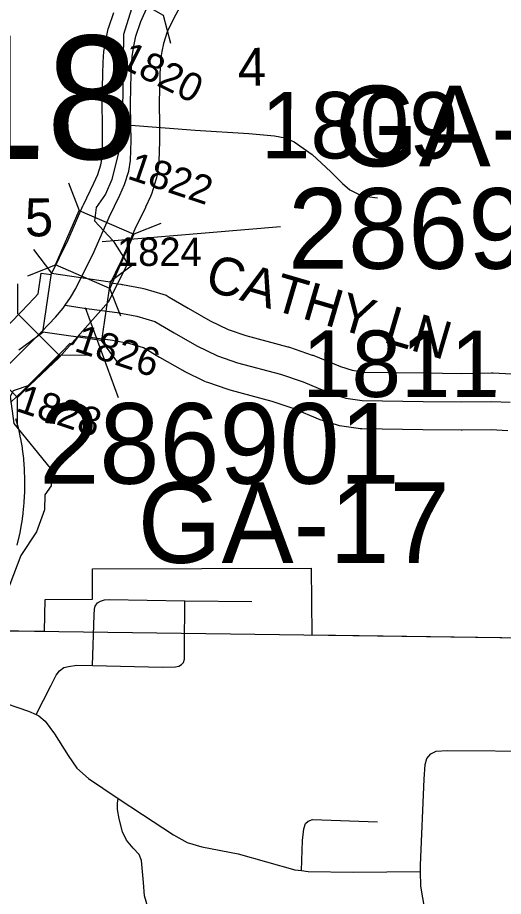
# Model space of a CAD drawing. Extents: x -132.8 to -73.3, y -60 to -26.
# Drawn here: x -121.403 to -120.892, y -47.631 to -46.704 of the extents above; entities that cross this region are included whole.
import ezdxf

# ---------------------------------------------------------------- set-up
doc = ezdxf.new("R2010")
doc.units = 0
for name, color, linetype in [('tdCoCityStreetMinor', 7, 'Continuous'), ('tdCoCorpBndry', 7, 'Continuous'), ('tdCoHydroRiver', 7, 'Continuous'), ('tdCoSecRdNmbr', 7, 'Continuous'), ('tdCoSecRdTxt', 7, 'Continuous'), ('tdCoSecRteBand', 7, 'Continuous'), ('tdCoSecRteCL', 7, 'Continuous'), ('tdCoSectLine', 7, 'Continuous'), ('tdCoSectLinePart', 7, 'Continuous'), ('tdCoSectNmbr', 7, 'Continuous'), ('tdCoStrucSec', 7, 'Continuous'), ('tdCoStrucSecCoName', 7, 'Continuous'), ('tdCoStrucSecFHWANum', 7, 'Continuous'), ('tdCoSurfBitum', 7, 'Continuous'), ('tdCoSurfGravelUnbanded', 7, 'Continuous')]:
    doc.layers.add(name, color=color, linetype=linetype)

msp = doc.modelspace()

# ---------------------------------------------------------------- linework, layer by layer
at = {"layer": 'tdCoCityStreetMinor'}
msp.add_line((-121.22694, -47.31903), (-121.15653, -47.32002), dxfattribs=at)
for points in [[(-121.32445, -47.38746), (-121.32275, -47.33408), (-121.32232, -47.32815), (-121.32135, -47.32471), (-121.31912, -47.32139), (-121.3158, -47.31939), (-121.31162, -47.31813), (-121.30641, -47.3179), (-121.22694, -47.31903)], [(-121.32445, -47.38746), (-121.25049, -47.38907), (-121.23693, -47.38882), (-121.23341, -47.3882), (-121.23045, -47.38623), (-121.22863, -47.38403), (-121.22757, -47.38054), (-121.22734, -47.36848), (-121.22694, -47.31903)], [(-121.38373, -47.43916), (-121.36837, -47.4088), (-121.3627, -47.39745), (-121.359, -47.39302), (-121.35456, -47.38956), (-121.34963, -47.38833), (-121.34099, -47.3871), (-121.32445, -47.38746)], [(-121.47354, -47.40947), (-121.42681, -47.42349), (-121.39179, -47.43558), (-121.38373, -47.43916)], [(-121.38373, -47.43916), (-121.3807, -47.44051), (-121.37428, -47.44593), (-121.36442, -47.45925), (-121.35012, -47.48218), (-121.34099, -47.4955), (-121.32866, -47.5066), (-121.2972, -47.52744)], [(-120.97879, -47.60466), (-120.97887, -47.59792), (-120.97492, -47.50717), (-120.97418, -47.49188), (-120.97221, -47.48547), (-120.96802, -47.48054), (-120.96259, -47.47783), (-120.951, -47.47709), (-120.84956, -47.47775)], [(-121.31347, -47.75773), (-121.30731, -47.74354), (-121.28462, -47.70087), (-121.27278, -47.67868), (-121.27, -47.67589), (-121.26448, -47.67036), (-121.26193, -47.66579), (-121.2607, -47.66139), (-121.2607, -47.657), (-121.26536, -47.6446), (-121.26941, -47.63018), (-121.27077, -47.61604), (-121.27274, -47.59297), (-121.27512, -47.58673), (-121.28145, -47.57987), (-121.28848, -47.5716), (-121.29288, -47.56263), (-121.2964, -47.54892), (-121.29808, -47.53901), (-121.29808, -47.53259), (-121.2972, -47.52744)], [(-121.2972, -47.52744), (-121.2717, -47.54433), (-121.23914, -47.56578), (-121.22459, -47.57392), (-121.20906, -47.57861), (-121.17108, -47.58576), (-121.11115, -47.60278), (-121.10439, -47.60362)], [(-121.10439, -47.60362), (-121.10316, -47.57178), (-121.10192, -47.55945), (-121.1002, -47.55403), (-121.09724, -47.55132), (-121.09255, -47.54984), (-121.02424, -47.5523)], [(-121.10439, -47.60362), (-121.09734, -47.6045), (-121.04975, -47.60524), (-120.97879, -47.60466)], [(-120.97334, -47.65354), (-120.97443, -47.64453), (-120.97862, -47.61987), (-120.97879, -47.60466)]]:
    msp.add_lwpolyline(points, dxfattribs=at)
at = {"layer": 'tdCoCorpBndry'}
msp.add_lwpolyline([(-122.63741, -47.30425), (-122.01168, -47.33499), (-121.798, -47.34549), (-121.57029, -47.3486), (-121.56097, -47.34961), (-121.54469, -47.34937), (-121.51658, -47.34813), (-121.48501, -47.34937), (-121.45889, -47.34964), (-121.45901, -47.35012), (-121.37487, -47.35127), (-121.37413, -47.31766), (-121.32448, -47.31743), (-121.32448, -47.28533), (-121.09419, -47.28473), (-121.09324, -47.35512), (-120.84351, -47.35854), (-120.71995, -47.35983), (-119.98355, -47.3675), (-119.85407, -47.36885)], dxfattribs=at)
at = {"layer": 'tdCoHydroRiver'}
for points in [[(-121.2815, -46.6893), (-121.29186, -46.72215), (-121.29321, -46.83097), (-121.30387, -46.87486), (-121.3106, -46.89045), (-121.32044, -46.90439), (-121.3224, -46.91853), (-121.30245, -46.93958), (-121.28732, -46.96366), (-121.30735, -47.00413), (-121.35943, -47.06267), (-121.3902, -47.09181), (-121.40773, -47.09765)], [(-121.40773, -47.09765), (-121.41105, -47.10387), (-121.40708, -47.13238), (-121.36888, -47.17916), (-121.36781, -47.19813), (-121.37438, -47.20741), (-121.3748, -47.22318), (-121.38333, -47.24662), (-121.39978, -47.27141), (-121.41508, -47.31202), (-121.42062, -47.34184), (-121.42765, -47.36847), (-121.47078, -47.38782), (-121.49175, -47.4046), (-121.50492, -47.42475), (-121.51882, -47.47171), (-121.52073, -47.48428), (-121.54937, -47.55135), (-121.55777, -47.57005), (-121.57324, -47.61696), (-121.57583, -47.71313)]]:
    msp.add_lwpolyline(points, dxfattribs=at)
at = {"layer": 'tdCoSecRteBand'}
for points in [[(-121.23209, -46.69277), (-121.23921, -46.70559), (-121.24556, -46.7193), (-121.24956, -46.73153), (-121.2513, -46.74005), (-121.25281, -46.74866), (-121.25359, -46.76456), (-121.25414, -46.79471), (-121.25388, -46.81727), (-121.25369, -46.83344), (-121.25368, -46.83406), (-121.2537, -46.83468), (-121.25433, -46.85588), (-121.25439, -46.85794), (-121.25473, -46.85997), (-121.25664, -46.87132), (-121.25697, -46.8733), (-121.25757, -46.87522), (-121.26193, -46.88929), (-121.26251, -46.89117), (-121.26333, -46.89295), (-121.26845, -46.90407), (-121.26856, -46.90432), (-121.26868, -46.90457), (-121.27964, -46.92728), (-121.29523, -46.96306), (-121.2955, -46.96367), (-121.2958, -46.96428), (-121.30546, -46.98398), (-121.29442, -46.98547), (-121.29361, -46.98558), (-121.29281, -46.98573), (-121.27209, -46.98968), (-121.27059, -46.98996), (-121.26912, -46.9904), (-121.25013, -46.99607), (-121.24668, -46.99711), (-121.24356, -46.99893), (-121.22348, -47.01069), (-121.20035, -47.0239), (-121.18137, -47.03306), (-121.16283, -47.03953), (-121.11878, -47.05133), (-121.11782, -47.05158), (-121.11687, -47.0519), (-121.09295, -47.06004), (-121.09206, -47.06035), (-121.09119, -47.0607), (-121.06306, -47.07229), (-121.05085, -47.0761), (-121.03786, -47.07796), (-120.97569, -47.07891), (-120.93571, -47.0794), (-120.90432, -47.07892), (-120.90331, -47.0789), (-120.90231, -47.07895), (-120.88308, -47.07994)], [(-121.42382, -47.03901), (-121.39904, -47.01418), (-121.3857, -47.00019), (-121.38159, -46.99537), (-121.37841, -46.9736), (-121.36793, -46.97513), (-121.34997, -46.93847), (-121.33441, -46.90277), (-121.33418, -46.90224), (-121.33393, -46.90172), (-121.32284, -46.87874), (-121.31866, -46.86966), (-121.31547, -46.85938), (-121.31424, -46.85205), (-121.31369, -46.83353), (-121.31388, -46.81797), (-121.31414, -46.79496), (-121.31415, -46.79451), (-121.31414, -46.79406), (-121.31357, -46.763), (-121.31356, -46.76255), (-121.31354, -46.7621), (-121.31265, -46.74385), (-121.31256, -46.74196), (-121.31223, -46.7401), (-121.31032, -46.72925), (-121.31025, -46.72886), (-121.31017, -46.72847), (-121.30801, -46.71786), (-121.30766, -46.71616), (-121.30712, -46.71451), (-121.30203, -46.69896)], [(-120.88704, -47.13981), (-120.90439, -47.13892), (-120.9352, -47.1394), (-120.93561, -47.13941), (-120.93603, -47.1394), (-120.97647, -47.13891), (-120.97652, -47.13891), (-120.97657, -47.13891), (-121.04069, -47.13792), (-121.04259, -47.13789), (-121.04447, -47.13762), (-121.06173, -47.13516), (-121.06413, -47.13482), (-121.06644, -47.13409), (-121.08222, -47.12916), (-121.08347, -47.12877), (-121.08469, -47.12827), (-121.11317, -47.11654), (-121.13526, -47.10903), (-121.17943, -47.0972), (-121.1805, -47.09691), (-121.18155, -47.09655), (-121.20276, -47.08915), (-121.20437, -47.08859), (-121.20592, -47.08784), (-121.22737, -47.07748), (-121.22831, -47.07703), (-121.22921, -47.07651), (-121.25338, -47.0627), (-121.25352, -47.06263), (-121.25365, -47.06255), (-121.27076, -47.05253), (-121.28482, -47.04833), (-121.30323, -47.04482), (-121.3372, -47.04025), (-121.33736, -47.04023), (-121.33753, -47.0402), (-121.33914, -47.03997), (-121.34577, -47.04941), (-121.34814, -47.04775), (-121.35583, -47.05582), (-121.35608, -47.05607), (-121.35632, -47.05632), (-121.38135, -47.08139), (-121.39713, -47.0972), (-121.3973, -47.09737), (-121.39748, -47.09754), (-121.41059, -47.11026)], [(-121.40524, -47.12711), (-121.40275, -47.13642), (-121.40257, -47.1371), (-121.40242, -47.13778), (-121.40037, -47.14719), (-121.40022, -47.14788), (-121.4001, -47.14857), (-121.39849, -47.15807), (-121.39838, -47.15876), (-121.39829, -47.15946), (-121.39713, -47.16902), (-121.39704, -47.16972), (-121.39699, -47.17042), (-121.39628, -47.18003), (-121.39623, -47.18064), (-121.39621, -47.18125), (-121.39587, -47.19155), (-121.39584, -47.19219), (-121.39585, -47.19284), (-121.39595, -47.20315), (-121.39596, -47.20379), (-121.39599, -47.20444), (-121.39654, -47.21473), (-121.39657, -47.21538), (-121.39663, -47.21602), (-121.39762, -47.22628), (-121.39769, -47.22692), (-121.39778, -47.22757), (-121.39921, -47.23777), (-121.3993, -47.23841), (-121.39942, -47.23905), (-121.40129, -47.24918), (-121.40141, -47.24982), (-121.40155, -47.25045), (-121.40386, -47.26049)]]:
    msp.add_lwpolyline(points, dxfattribs=at)
at = {"layer": 'tdCoSecRteCL'}
for points in [[(-121.28388, -46.81762), (-121.28415, -46.79461), (-121.28357, -46.76355), (-121.28269, -46.74531), (-121.28077, -46.73446), (-121.27861, -46.72385), (-121.27352, -46.70829), (-121.26597, -46.69199), (-121.25279, -46.66825), (-121.25085, -46.66521)], [(-121.35306, -47.00762), (-121.34737, -46.99951), (-121.34175, -46.98987), (-121.32274, -46.95107), (-121.30691, -46.91476), (-121.2957, -46.89153), (-121.29058, -46.88041), (-121.28622, -46.86634), (-121.28431, -46.85499), (-121.28369, -46.83379), (-121.28388, -46.81762)], [(-121.28388, -46.81762), (-121.21623, -46.82292), (-121.15976, -46.82662), (-121.13263, -46.82908), (-121.12129, -46.83105), (-121.11192, -46.83525), (-121.09318, -46.84881), (-121.07345, -46.86706), (-121.06112, -46.87914), (-121.05323, -46.8858), (-121.0441, -46.89049), (-121.03522, -46.89295), (-121.02437, -46.89443)], [(-121.44632, -47.10312), (-121.41836, -47.07601), (-121.40258, -47.0602), (-121.37756, -47.03513), (-121.36341, -47.02028), (-121.35519, -47.01064), (-121.35306, -47.00762)], [(-121.35306, -47.00762), (-121.33319, -47.01052), (-121.29842, -47.0152), (-121.27771, -47.01915), (-121.25872, -47.02482), (-121.2385, -47.03666), (-121.21433, -47.05047), (-121.19287, -47.06082), (-121.17167, -47.06822), (-121.12654, -47.08031), (-121.10262, -47.08844), (-121.07327, -47.10053), (-121.05749, -47.10546), (-121.04022, -47.10793), (-120.97611, -47.10891), (-120.93566, -47.10941), (-120.90385, -47.10891), (-120.88462, -47.1099)]]:
    msp.add_lwpolyline(points, dxfattribs=at)
at = {"layer": 'tdCoSectLine'}
msp.add_lwpolyline([(-121.79838, -47.34549), (-120.84389, -47.35854)], dxfattribs=at)
at = {"layer": 'tdCoSectLinePart'}
msp.add_lwpolyline([(-121.42853, -47.35055), (-121.37525, -47.35127)], dxfattribs=at)
at = {"layer": 'tdCoStrucSec'}
for points in [[(-121.24172, -46.73173), (-121.24969, -46.70218), (-121.30392, -46.67098)], [(-121.34977, -46.87856), (-121.33832, -46.90767), (-121.28097, -46.93266)], [(-121.39243, -46.97647), (-121.36331, -46.96503), (-121.33832, -46.90767)], [(-121.25248, -46.92147), (-121.28097, -46.93266), (-121.30596, -46.99002)], [(-121.38632, -46.94885), (-121.36763, -46.97393), (-121.30572, -46.98297)], [(-121.28064, -46.96428), (-121.30572, -46.98297), (-121.31476, -47.04487)], [(-121.29452, -47.01913), (-121.30596, -46.99002), (-121.36331, -46.96503)], [(-121.40174, -47.05453), (-121.37666, -47.03584), (-121.36763, -46.97393)], [(-121.40327, -46.98493), (-121.40324, -47.01621), (-121.35897, -47.0604)], [(-121.29647, -47.06942), (-121.31476, -47.04487), (-121.37666, -47.03584)], [(-121.40313, -47.13596), (-121.40316, -47.10468), (-121.44744, -47.06048)], [(-121.32836, -47.06037), (-121.35897, -47.0604), (-121.40316, -47.10468)]]:
    msp.add_lwpolyline(points, dxfattribs=at)
at = {"layer": 'tdCoStrucSecFHWANum'}
for p, q in [((-121.1262, -46.92499), (-121.31428, -46.9408)), ((-121.29689, -47.1053), (-121.33166, -47.0104))]:
    msp.add_line(p, q, dxfattribs=at)
at = {"layer": 'tdCoSurfBitum'}
for points in [[(-121.35306, -47.00762), (-121.34737, -46.99951), (-121.34175, -46.98987), (-121.32274, -46.95107), (-121.30691, -46.91476), (-121.2957, -46.89153), (-121.29058, -46.88041), (-121.28622, -46.86634), (-121.28431, -46.85499), (-121.28369, -46.83379), (-121.28388, -46.81762), (-121.28415, -46.79461), (-121.28357, -46.76355), (-121.28269, -46.74531), (-121.28077, -46.73446), (-121.27861, -46.72385), (-121.27352, -46.70829), (-121.26597, -46.69199), (-121.25279, -46.66825), (-121.25085, -46.66521)], [(-121.44632, -47.10312), (-121.41836, -47.07601), (-121.40258, -47.0602), (-121.37756, -47.03513), (-121.36341, -47.02028), (-121.35519, -47.01064), (-121.35306, -47.00762)], [(-121.35306, -47.00762), (-121.33319, -47.01052), (-121.29842, -47.0152), (-121.27771, -47.01915), (-121.25872, -47.02482), (-121.2385, -47.03666), (-121.21433, -47.05047), (-121.19287, -47.06082), (-121.17167, -47.06822), (-121.12654, -47.08031), (-121.10262, -47.08844), (-121.07327, -47.10053), (-121.05749, -47.10546), (-121.04022, -47.10793), (-120.97611, -47.10891), (-120.93566, -47.10941), (-120.90385, -47.10891), (-120.88462, -47.1099)]]:
    msp.add_lwpolyline(points, dxfattribs=at)
at = {"layer": 'tdCoSurfGravelUnbanded'}
msp.add_lwpolyline([(-121.28388, -46.81762), (-121.21623, -46.82292), (-121.15976, -46.82662), (-121.13263, -46.82908), (-121.12129, -46.83105), (-121.11192, -46.83525), (-121.09318, -46.84881), (-121.07345, -46.86706), (-121.06112, -46.87914), (-121.05323, -46.8858), (-121.0441, -46.89049), (-121.03522, -46.89295), (-121.02437, -46.89443)], dxfattribs=at)

# ---------------------------------------------------------------- texts
at = {"layer": 'tdCoSecRdNmbr'}
for s, height, rotation, p in [('1820', 0.03, 333.35139, (-121.29783, -46.75536)), ('1809', 0.07, 359.90937, (-121.14703, -46.85264)), ('1822', 0.03, 341.48386, (-121.28884, -46.87381)), ('1824', 0.03, 359.9094, (-121.29858, -46.96607)), ('1826', 0.03, 341.48386, (-121.3447, -47.0555)), ('1811', 0.07, 359.90942, (-121.10365, -47.10415)), ('1828', 0.03, 341.48386, (-121.40604, -47.11868))]:
    msp.add_text(s, height=height, rotation=rotation, dxfattribs=at).set_placement(p)
at = {"layer": 'tdCoSecRdTxt'}
for s, rotation, p in [('4', 0.46091, (-121.17109, -46.77637)), ('5', 0.46091, (-121.39536, -46.93507)), ('CATHY LN', 343.66455, (-121.20771, -46.99091))]:
    msp.add_text(s, height=0.04, rotation=rotation, dxfattribs=at).set_placement(p)
at = {"layer": 'tdCoSectNmbr'}
msp.add_text('18', height=0.13, rotation=359.90917, dxfattribs=at).set_placement((-121.46975, -46.85321))
at = {"layer": 'tdCoStrucSecCoName'}
for s, p in [('GA-20', (-121.06916, -46.86115)), ('GA-17', (-121.27677, -47.27917))]:
    msp.add_text(s, height=0.085, dxfattribs=at).set_placement(p)
at = {"layer": 'tdCoStrucSecFHWANum'}
for s, p in [('286930', (-121.11842, -46.96912)), ('286901', (-121.3803, -47.19575))]:
    msp.add_text(s, height=0.085, dxfattribs=at).set_placement(p)

doc.saveas('drawing.dxf')
